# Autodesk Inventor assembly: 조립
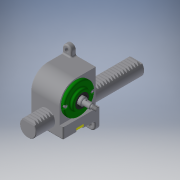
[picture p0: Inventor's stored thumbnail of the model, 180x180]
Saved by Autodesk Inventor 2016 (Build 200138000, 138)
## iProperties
Created: 2019-06
Part Number: 조립
Material: 일반
Document SubType Name: Assembly
Designer: 605-11
Author: 605-11
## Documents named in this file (10)
- C:\Users\605-11\Desktop\390604v1036\답안조립품.iam
- C:\Users\605-11\Desktop\390604v1036\본체.ipt
- C:\Users\605-11\Desktop\390604v1036\누름쇠.ipt
- C:\Users\605-11\Desktop\390604v1036\뒤커버.ipt
- C:\Users\605-11\Desktop\390604v1036\래크.ipt
- C:\Users\605-11\Desktop\390604v1036\베어링 6003.ipt
- C:\Users\605-11\Desktop\390604v1036\볼트 M4.ipt
- C:\Users\605-11\Desktop\390604v1036\앞커버.ipt
- C:\Users\605-11\Desktop\390604v1036\오일 실 17 30 5.ipt
- C:\Users\605-11\Desktop\390604v1036\피니언.ipt
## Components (1 placed, 1 different names)
1. 피니언:1 — 각도:4
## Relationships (1: Angle 1)
- 각도:4 [Angle]: 피니언:1
